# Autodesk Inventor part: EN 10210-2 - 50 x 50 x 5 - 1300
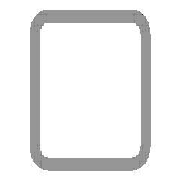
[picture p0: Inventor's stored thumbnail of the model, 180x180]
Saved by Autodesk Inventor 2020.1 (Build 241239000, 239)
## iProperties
IsCustomPart: 1
_CCFamilyMember: 16
_CCFamilyDisplayName: DIN EN 10210-2 (USAS B17.1 quadratisch) - Rohrleitung — In Klammern angegebene Größen wurden aufgehoben
_FrameMemberDoc: Frame Member File
_Version: 15.0.0
_GetPNFromCC: 1
Created: 2019-10
Part Number: EN 10210-2 - 50 x 50 x 5 - 1300
Material: Stahl, weich
Description: Rohrleitung
Document SubType Name: Modeling
Standard: DIN
Designer: lutzd
Standard Revision: 2006-07
Standards Organization: DIN
Language: de-DE
Size Designation: 50 x 50 x 5
Categories: <MemberInstance><Categories><Category DisplayName="Profile" InternalName="089c4875-fa83-4c05-b084-43b9cc11f5ed" Mnemonic="GRDR"><CategoryParameter DisplayName="
Stock Number: 50 x 50 x 5
Mass: 8908.02 g
Surface Area: 4419.18 cm^2
Volume: 1134.78 cm^3
Density: 7.85 g/cm^3
Appearance: Halbpoliert
G_L: 1300,000 mm
G_W: 50,000 mm
G_H: 50,000 mm
Dimensions: 50x50x1300 mm
Mass: 8,908 kg
DocNumber: ADSK-014089
Folder: .
+90B3A399-8AA0-4C12-9615-A854440BD933+SCHNITTDETAIL1: Schnittwinkel 90,00 grd
+31BFE8C6-649C-4DC8-99C7-47ABF7C92EA1+SCHNITTDETAIL2: Schnittwinkel 90,00 grd
Title: Profil-Bauteil
Author: lutzd
Revision Number: -
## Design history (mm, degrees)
node "Startebene"
node "Endebene"
sketch "Skizze"
  geometry: L1 (-25, -17.5)-(-25, 17.5); L2 (-17.5, 25)-(17.5, 25); L3 (25, 17.5)-(25, -17.5); L4 (17.5, -25)-(-17.5, -25); L5 (-15, 20)-(15, 20); L6 (20, 15)-(20, -15); L7 (15, -20)-(-15, -20); L8 (-20, -15)-(-20, 15); L9 (0, 37.175)-(0, -37.175) reference; L10 (-37.175, 0)-(37.175, 0) reference; A1 r 7.5 centre (-17.5, -17.5) between (-25, -17.5) and (-17.5, -25); A2 r 7.5 centre (-17.5, 17.5) between (-17.5, 25) and (-25, 17.5); A3 r 7.5 centre (17.5, 17.5) between (25, 17.5) and (17.5, 25); A4 r 7.5 centre (17.5, -17.5) between (17.5, -25) and (25, -17.5); A5 r 5 centre (-15, -15) between (-20, -15) and (-15, -20); A6 r 5 centre (-15, 15) between (-15, 20) and (-20, 15); A7 r 5 centre (15, 15) between (20, 15) and (15, 20); A8 r 5 centre (15, -15) between (15, -20) and (20, -15)
  constraints: 16 end point, 16 point on circle, 16 tangent, 8 centre point, 6 equal radius, 4 parallel, 2 perpendicular, 2 other
  dimensions: "d7" = 7.5 radius of A1 (= G_IR); "d10" = 50 distance between parallel lines of L2 L4 (= G_H); "d11" = 50 distance between parallel lines of L1 L3 (= G_W); "d12" = 5 distance between parallel lines of L3 L6 (= G_T); "d15" = 25 distance between parallel lines of L2 L10 (= 0.5 x d10); "d16" = 25 distance between parallel lines of L9 L3 (= 0.5 x d11); "d19" = 5 radius of A5 (= G_T); "d20" = 5 distance between parallel lines of L4 L7 (= G_T)
extrude "Körper" new body sketch "Skizze" stored distance "d3" = 1300 (= G_L); taper "d4" = 0 deg
node "Driven Length"
  sketch "Sketch3"
    geometry: L1 (0, 0)-(10, 0) reference
    constraints: 2 end point, 1 horizontal
  workplane "Work Plane3"
  sketch "Sketch4"
    geometry: L1 (-2, 25)-(12, 25) reference; L2 (-2, 1325)-(12, 1325) reference
    dimensions: "d18" = 1300 distance between parallel lines of L1 L2 (derived)
workplane "Arbeitsebene4"
feature "Trennen1"
workplane "Arbeitsebene5"
feature "Trennen2"
sketch "Skizze5"
  geometry: L1 (-35, 0)-(0, 0) reference; L2 (-17.5, 0)-(-17.5, 495); 3 further points
  constraints: 2 end point, 1 coincident, 1 midpoint, 1 point on line, 1 vertical
  dimensions: "d21" = 96 distance of point (-17.5, 399) point (-17.5, 495); "d22" = 399 distance from line of L1 point (-17.5, 399)
hole "Bohrung1" sketch "Skizze5" at (-17.5, 495), (-17.5, 399) diameter "d23" = 6.647; stored, may be unused: countersink angle "d27" = 90 deg, drill point angle "d29" = 0 deg; dims "d24" = 16, "d25" = 4, "d26" = 2, "d28" = 8
body "Solid1"
other parameters: "G_W" = 50 [user parameter; used in 1 equation term], "G_H" = 50 [user parameter; used in 1 equation term], "G_T" = 5 [user parameter; used in 3 equation terms], "G_IR" = 7.5 [user parameter; used in 1 equation term], "G_L" = 1300 (= d18) [user parameter; used in 1 equation term], "G_OFFSET_START" = -25 [user parameter; used in 1 equation term], "d13" = 25 (= -G_OFFSET_START), "d14" = 1325 (= G_OFFSET_END + B_L), "B_L" = 1375 [user parameter; used in 1 equation term], "d17" = 90 deg
